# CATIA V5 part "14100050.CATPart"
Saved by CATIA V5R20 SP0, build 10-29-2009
Part number: 14100050
Definition: NONE
Nomenclature: 14100050
Source: Unknown
Description: 14100050
Bounding box of the stored display mesh (mm): x -25 to 100, y -64 to 53.915, z -54.1 to 54.1
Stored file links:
  C:\Users\Utente\Desktop\IO LAVORO\3D X SITO CF\X SITO\PLASTICA\RF2\14100050.CATPart
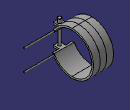
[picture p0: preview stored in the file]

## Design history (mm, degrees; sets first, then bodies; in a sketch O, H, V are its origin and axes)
Body1 "14100050" (main body)
  Solid1: solid without history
